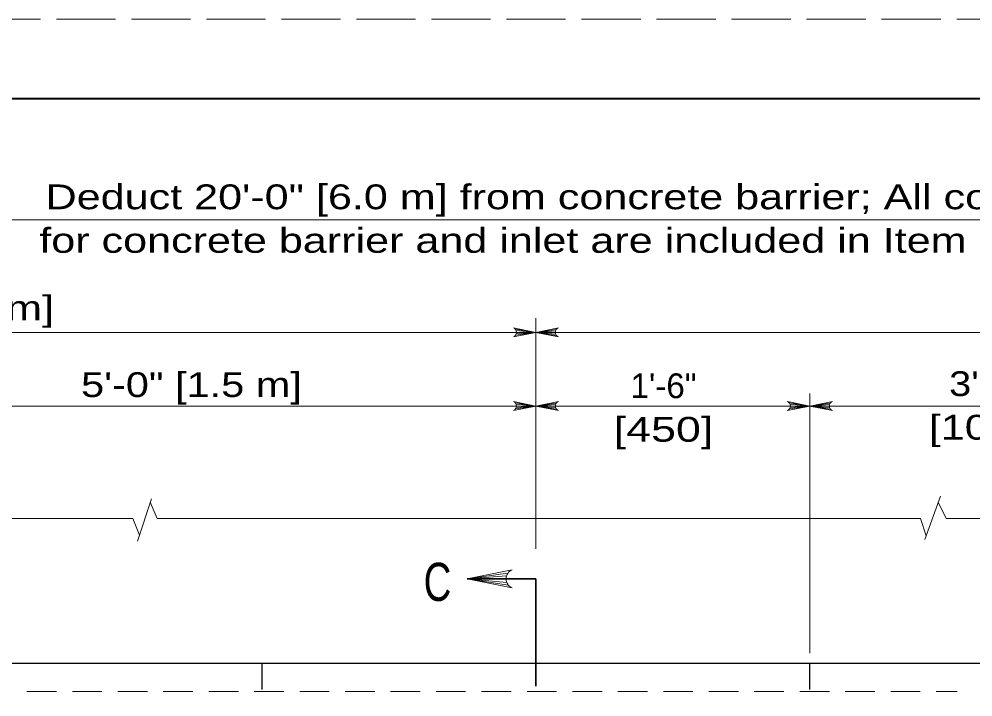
# Model space of a CAD drawing. Extents: x 1083.1 to 1123, y 697.4 to 741.4.
# Drawn here: x 1091.03 to 1097.03, y 737.09 to 741.35 of the extents above; entities that cross this region are included whole.
import ezdxf
from ezdxf.enums import TextEntityAlignment as Align

# ---------------------------------------------------------------- set-up
doc = ezdxf.new("R2010")
doc.units = 0
doc.header["$LTSCALE"] = 0.062
doc.linetypes.add('LONG_DASHED', pattern=[7.5, 6, -1.5])
doc.linetypes.add('MEDIUM_DASHED', pattern=[4.5, 3, -1.5])
doc.layers.add('1', color=7, linetype='Continuous', lineweight=13)

msp = doc.modelspace()

# ---------------------------------------------------------------- linework, layer by layer
at = {"layer": '1', "lineweight": 25}
for p, q in [((1085.12642, 740.85408), (1116.62642, 740.85408)), ((1090.31492, 737.30308), (1097.19883, 737.30308))]:
    msp.add_line(p, q, dxfattribs=at)
at = {"layer": '1'}
for p, q in [((1086.34033, 740.09192), (1102.18317, 740.09192)), ((1094.28367, 738.02308), (1094.28367, 739.474)), ((1094.15392, 739.40375), (1094.28367, 739.38392)), ((1086.34033, 739.38392), (1102.18317, 739.38392)), ((1094.1555, 739.366), (1094.28367, 739.38392)), ((1094.15883, 739.39542), (1094.28367, 739.38392)), ((1094.15983, 739.37483), (1094.28367, 739.38392)), ((1094.16108, 739.38392), (1094.28367, 739.38392)), ((1094.41183, 739.40183), (1094.28367, 739.38392)), ((1094.4075, 739.393), (1094.28367, 739.38392)), ((1094.40617, 739.38392), (1094.28367, 739.38392)), ((1094.40842, 739.37242), (1094.28367, 739.38392)), ((1094.41333, 739.36408), (1094.28367, 739.38392)), ((1096.007, 737.36708), (1096.007, 738.99933)), ((1094.15392, 738.9405), (1094.28367, 738.92067)), ((1094.15883, 738.93225), (1094.28367, 738.92067)), ((1094.41183, 738.93867), (1094.28367, 738.92067)), ((1094.4075, 738.92975), (1094.28367, 738.92067)), ((1095.87725, 738.9405), (1096.007, 738.92067)), ((1095.88217, 738.93225), (1096.007, 738.92067)), ((1096.13517, 738.93867), (1096.007, 738.92067)), ((1096.13083, 738.92975), (1096.007, 738.92067)), ((1098.24367, 738.92067), (1090.31492, 738.92067)), ((1094.1555, 738.90275), (1094.28367, 738.92067)), ((1094.15983, 738.91167), (1094.28367, 738.92067)), ((1094.16108, 738.92067), (1094.28367, 738.92067)), ((1094.40617, 738.92067), (1094.28367, 738.92067)), ((1094.40842, 738.90917), (1094.28367, 738.92067)), ((1094.41333, 738.90092), (1094.28367, 738.92067)), ((1095.87875, 738.90275), (1096.007, 738.92067)), ((1095.88308, 738.91167), (1096.007, 738.92067)), ((1095.88442, 738.92067), (1096.007, 738.92067)), ((1096.1295, 738.92067), (1096.007, 738.92067)), ((1096.13175, 738.90917), (1096.007, 738.92067)), ((1096.13667, 738.90092), (1096.007, 738.92067)), ((1091.86458, 738.33775), (1091.77767, 738.07067)), ((1096.8285, 738.35433), (1096.72958, 738.08217)), ((1091.9, 738.21267), (1091.85767, 738.31642)), ((1096.86367, 738.21267), (1096.81483, 738.31667)), ((1091.9, 738.21267), (1096.70217, 738.21267)), ((1096.70217, 738.21267), (1096.7375, 738.10392)), ((1096.86367, 738.21267), (1102.18317, 738.21267)), ((1094.10742, 737.86983), (1093.851, 737.83392)), ((1094.09867, 737.85208), (1093.851, 737.83392)), ((1094.09608, 737.83392), (1093.851, 737.83392)), ((1094.10058, 737.81092), (1093.851, 737.83392)), ((1094.11042, 737.79425), (1093.851, 737.83392))]:
    msp.add_line(p, q, dxfattribs=at)
at = {"layer": '1', "lineweight": 35}
for p, q in [((1094.28367, 737.83392), (1093.851, 737.83392)), ((1094.28367, 737.83392), (1094.28367, 737.5115)), ((1094.28367, 737.15933), (1094.28367, 737.73492))]:
    msp.add_line(p, q, dxfattribs=at)
at = {"layer": '1', "linetype": 'LONG_DASHED', "lineweight": 25}
for p, q in [((1092.56042, 733.83392), (1092.56042, 737.30308)), ((1096.007, 733.83392), (1096.007, 737.30308))]:
    msp.add_line(p, q, dxfattribs=at)
at = {"layer": '1', "linetype": 'MEDIUM_DASHED'}
msp.add_line((1089.93733, 737.12525), (1096.93425, 737.12525), dxfattribs=at)
at = {"layer": '1', "linetype": 'LONG_DASHED'}
msp.add_lwpolyline([(1083.12642, 719.35408), (1117.12642, 719.35408), (1117.12642, 741.35408), (1083.12642, 741.35408)], close=True, dxfattribs=at)
at = {"layer": '1', "lineweight": 40}
msp.add_lwpolyline([(1085.12642, 740.85408), (1116.62642, 740.85408), (1116.62642, 719.85408), (1085.12642, 719.85408)], close=True, dxfattribs=at)
at = {"layer": '1'}
for points in [[(1094.14208, 739.41225), (1094.28367, 739.38392), (1094.14208, 739.35558)], [(1094.42525, 739.35558), (1094.28367, 739.38392), (1094.42525, 739.41225)], [(1094.14208, 738.949), (1094.28367, 738.92067), (1094.14208, 738.89242)], [(1094.42525, 738.89242), (1094.28367, 738.92067), (1094.42525, 738.949)], [(1095.86533, 738.949), (1096.007, 738.92067), (1095.86533, 738.89242)], [(1096.14858, 738.89242), (1096.007, 738.92067), (1096.14858, 738.949)], [(1086.34033, 738.21267), (1091.74717, 738.21267), (1091.79, 738.10867)], [(1094.13417, 737.77725), (1093.851, 737.83392), (1094.13417, 737.89058)]]:
    msp.add_lwpolyline(points, dxfattribs=at)
for centre, radius, start, end in [((1094.13062, 739.38388), 0.03056, 292.08782, 67.91395), ((1094.43669, 739.38394), 0.03056, 112.08782, 247.91395), ((1094.13062, 738.92067), 0.03056, 292.08782, 67.91395), ((1094.43669, 738.92074), 0.03056, 112.08782, 247.91395), ((1095.85394, 738.92067), 0.03056, 292.08782, 67.91395), ((1096.16001, 738.92074), 0.03056, 112.08782, 247.91395), ((1094.15706, 737.83398), 0.06112, 112.08782, 247.91395)]:
    msp.add_arc(centre, radius, start, end, dxfattribs=at)

# ---------------------------------------------------------------- texts
for s, width, p in [('Deduct 20\'-0" [6.0 m] from concrete barrier; All costs', 1.3, (1094.33979, 740.15825)), ('for concrete barrier and inlet are included in Item 604', 1.3, (1094.33979, 739.88425)), ('3\'-6"', 1.2, (1097.132, 738.98325)), ('[1050]', 1.3, (1097.132, 738.70925)), ('[450]', 1.35, (1095.08617, 738.69608))]:
    msp.add_text(s, height=0.156, dxfattribs=dict(at, width=width)).set_placement(p, align=Align.CENTER)
for s, height, width, p in [('10\'-0" [3.0 m]', 0.156, 1.3, (1089.6565, 739.4595)), ('5\'-0" [1.5 m]', 0.156, 1.25, (1091.42192, 738.97708)), ('C', 0.24, 0.75, (1093.57725, 737.69483))]:
    msp.add_text(s, height=height, dxfattribs=dict(at, width=width)).set_placement(p)
msp.add_text('1\'-6"', height=0.156, dxfattribs=at).set_placement((1095.08621, 738.97008), align=Align.CENTER)

doc.saveas('drawing.dxf')
